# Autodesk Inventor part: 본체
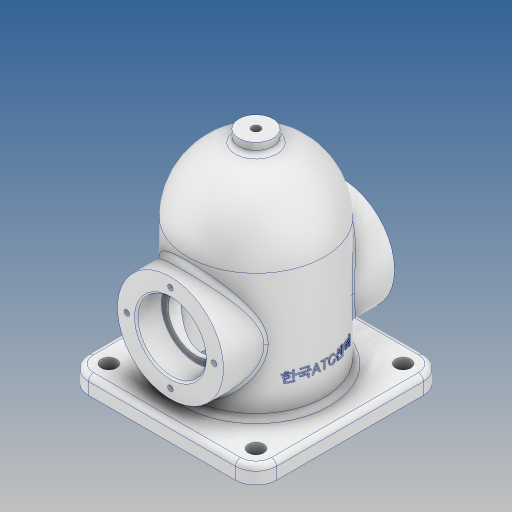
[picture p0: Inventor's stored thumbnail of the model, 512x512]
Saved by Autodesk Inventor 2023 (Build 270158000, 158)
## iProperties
Created: 2025-04
Part Number: 본체
Material: 알루미늄 6061
Document SubType Name: Modeling
Designer: Admin
Mass: 865.986 g
Surface Area: 800.738 cm^2
Volume: 320.735 cm^3
Density: 2.7 g/cm^3
Appearance: 알루미늄 - 평지
Author: Admin
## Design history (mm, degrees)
sketch "스케치1"
  geometry: L1 (40, 84)-(40, 0); L2 (0, 140.726)-(0, 0); L3 (0, 0)-(40, 0); L4 (0, -28.145)-(0, 168.871) reference; A1 r 40 centre (0, 84) between (40, 84) and (0, 124); 1 further point
  constraints: 6 end point, 2 point on circle, 2 vertical, 1 centre point, 1 perpendicular, 1 point on line, 1 tangent
  dimensions: "d0" = 80 diameter of A1; "d1" = 84 distance of A1.centre L2.end
revolve "회전1" sketch "스케치1" stored, may be unused: angle "d2" = 90 deg
sketch "스케치2"
  geometry: L1 (-40, 0)-(-40, 84) reference; L2 (40, 0)-(40, 84) reference; L3 (32, 0)-(32, 84); L4 (0, 116)-(0, 0); L5 (32, 0)-(0, 0); L6 (40, 0)-(-40, 0) reference; L7 (0, -24.8)-(0, 148.8) reference; A1 r 40 centre (0, 84) between (40, 84) and (-40, 84) reference; A2 r 32 centre (0, 84) between (32, 84) and (0, 116); 1 further point
  constraints: 6 end point, 2 point on circle, 1 centre point, 1 collinear, 1 parallel, 1 vertical
  dimensions: "d3" = 8 radial gap between concentric circles of A1 A2; "d4" = 8 distance between parallel lines of L2 L3
revolve "회전2" sketch "스케치2" stored, may be unused: angle "d5" = 90 deg
sketch "스케치3"
  geometry: L1 (-55, -55)-(55, -55); L2 (55, -55)-(55, 55); L3 (55, 55)-(-55, 55); L4 (-55, 55)-(-55, -55); L5 (-55, -55)-(55, 55); L6 (55, -55)-(-55, 55); 1 further point
  constraints: 12 end point, 2 midpoint, 2 parallel, 1 horizontal, 1 perpendicular
  dimensions: "d6" = 110 distance of L3.end L2.end; "d7" = 110 distance of L2.end L1.end
extrude "돌출1" join sketch "스케치3" distance "d8" = 10; taper "d9" = 0 deg
sketch "스케치4"
  geometry: C1 r 32 at (55, -55) reference; 1 further point
extrude "돌출2" cut sketch "스케치4" distance "d10" = 10; taper "d11" = 0 deg
node "작업 평면1"
sketch "스케치5"
  geometry: C1 r 10 at (0, 0); 1 further point
  constraints: 1 centre point, 1 coincident
  dimensions: "d13" = 20 diameter of C1
extrude "돌출3" join sketch "스케치5" distance "d14" = 12; taper "d15" = 0 deg
sketch "스케치6"
  geometry: C1 r 31 at (0, 48); 1 further point
  constraints: 1 centre point
  dimensions: "d16" = 62 diameter of C1; "d17" = 48 distance of C1.centre point (0, 0)
extrude "돌출4" join sketch "스케치6" stored distance "d18" = 100; taper "d19" = 0 deg
sketch "스케치7"
  geometry: C1 r 20 at (0, 0); 1 further point
  constraints: 1 centre point
  dimensions: "d20" = 40 diameter of C1
extrude "돌출5" cut sketch "스케치7" distance "d21" = 15; taper "d22" = 0 deg
sketch "스케치8"
  geometry: C1 r 20 at (0, 0); 1 further point
  constraints: 1 centre point
  dimensions: "d23" = 40 diameter of C1
extrude "돌출6" cut sketch "스케치8" distance "d24" = 15; taper "d25" = 0 deg
sketch "스케치9"
  geometry: C1 r 16.5 at (0, 0); 1 further point
  constraints: 1 centre point
  dimensions: "d26" = 33 diameter of C1
extrude "돌출7" cut sketch "스케치9" extent not by distance; stored distance "d27" = 0; taper "d28" = 0 deg
sketch "스케치10"
  geometry: L1 (116, 0)-(0, 0); L2 (0, -32)-(0, 32) reference; L3 (0, 0)-(0, -32); L4 (0, -32)-(84, -32); L5 (-25.8, 0)-(154.8, 0) reference; A1 r 32 centre (84, 0) between (84, -32) and (116, 0); A2 r 32 centre (84, 0) between (84, -32) and (84, 32) reference
  constraints: 6 end point, 3 point on circle, 1 centre point, 1 collinear, 1 horizontal, 1 perpendicular
revolve "회전3" sketch "스케치10" stored, may be unused: angle "d30" = 90 deg
sketch "스케치11"
  geometry: A1 r 25.5 centre (0, 0) between (0, 25.5) and (25.5, 0); 3 further points
  constraints: 4 point on circle, 1 centre point
  dimensions: "d31" = 51 diameter of A1
hole "구멍1" sketch "스케치11" at (0, 25.5), (25.5, 0), (0, -25.5), (-25.5, 0) diameter "d32" = 3.242; stored, may be unused: countersink angle "d36" = 90 deg, drill point angle "d38" = 118 deg; dims "d33" = 8, "d34" = 4, "d35" = 2, "d37" = 10
sketch "스케치12"
  geometry: 2 further points
  constraints: 1 coincident
hole "구멍2" sketch "스케치12" at (0, 0) diameter "d39" = 4.917; stored, may be unused: countersink angle "d43" = 90 deg, drill point angle "d45" = 118 deg; dims "d40" = 20, "d41" = 4, "d42" = 2, "d44" = 21
chamfer "모따기1" distance "d46" = 1; stored, may be unused: second distance "d47" = 2, angle "d48" = 45 deg
fillet "모깎기1" dims "d49" = 0.3
sketch "스케치13"
  geometry: L1 (98, -12)-(12, -12); L2 (12, -12)-(12, -98); L3 (12, -98)-(98, -98); L4 (98, -98)-(98, -12); L5 (98, -12)-(12, -98); L6 (12, -12)-(98, -98); C1 r 2.458 at (55, -55) reference; C2 r 4.5 at (98, -98); C3 r 4.5 at (12, -98); C4 r 4.5 at (12, -12); C5 r 4.5 at (98, -12); 1 further point
  constraints: 12 end point, 4 centre point, 4 coincident, 2 midpoint, 2 parallel, 1 horizontal, 1 perpendicular
  dimensions: "d50" = 86 distance of L3.end L2.end; "d51" = 86 distance of L2.end L1.end; "d52" = 9 diameter of C2; "d53" = 9 diameter of C3; "d54" = 9 diameter of C4; "d55" = 9 diameter of C5
extrude "돌출8" cut sketch "스케치13" distance "d56" = 10; taper "d57" = 0 deg
fillet "모깎기2" dims "d58" = 12
sketch "스케치14"
  geometry: 1 further point
fillet "모깎기3" dims "d59" = 3
fillet "모깎기4" dims "d60" = 3
node "작업 평면2"
sketch "스케치15"
  geometry: L1 (-25.8, 0)-(154.8, 0) reference; L2 (0, -43)-(0, 43) reference; 2 further points
  constraints: 1 point on line, 1 other
  dimensions: "d62" = 30 distance from line of point (30, 0) L2
feature "엠보싱1" sketch "스케치15" dims "d63" = 0.5, "d64" = 0
node "솔리드1"
mirror "미러1"
feature "A9D066F2-1C7D-4E18-AEED-F7BC21143FA4" dims "d32" = 3.242, "d33" = 8, "d34" = 4, "d35" = 2, "d36" = 90 deg, "d37" = 10, "d38" = 118 deg
other parameters: "d12" = 129, "d61" = 82.55
